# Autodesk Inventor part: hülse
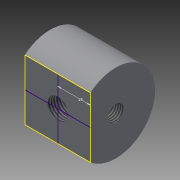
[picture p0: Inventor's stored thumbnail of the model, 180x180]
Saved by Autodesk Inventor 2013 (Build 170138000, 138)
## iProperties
Created: 2012-11
Part Number: hülse
Material: Allgemein
Document SubType Name: Modeling
Designer: macuser
Density: 1 g/cm^3
Author: macuser
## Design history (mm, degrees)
sketch "Skizze1"
  geometry: L1 (0, -42)-(0, 42) reference; L2 (-29.114, 0)-(39.852, 0) reference; L3 (-19.261, 23)-(-19.261, -23); A1 r 30 centre (0, 0) between (-19.261, -23) and (-19.261, 23); 1 further point
  constraints: 2 end point, 2 point on circle, 1 centre point, 1 coincident, 1 perpendicular
  dimensions: "d0" = 60 diameter of A1; "d2" = 46 distance of L3.end L3.start
extrude "Extrusion1" new body sketch "Skizze1" distance "d3" = 50; taper "d4" = 0 deg
sketch "Skizze3"
  geometry: L1 (0, 46)-(0, 0) reference; L2 (0, 0)-(50, 0) reference; L3 (50, 46)-(50, 0) reference; L4 (0, 46)-(50, 46) reference; L5 (0, 23)-(50, 23); L6 (25, 46)-(25, 0)
  constraints: 4 end point, 3 midpoint, 1 perpendicular
  dimensions: "d8" = 25 distance between parallel lines of L3 L6
hole "Bohrung1" diameter "d11" = 16; stored, may be unused: countersink angle "d15" = 90 deg, drill point angle "d17" = 118 deg; dims "d9" = 25, "d10" = 23, "d12" = 100, "d13" = 4, "d14" = 2, "d16" = 8
sketch "Skizze4"
  geometry: C1 r 6 at (0, 0); A1 r 30 centre (0, 0) between (23, -19.261) and (-23, -19.261) reference
  constraints: 1 centre point, 1 coincident
  dimensions: "d38" = 12 diameter of C1
extrude "Extrusion3" cut sketch "Skizze4" distance "d39" = 16; taper "d40" = 0 deg
feature "Gewinde1" dims "d41" = 10, "d42" = 0
sketch "Skizze5"
  geometry: C1 r 6 at (0, 0); A1 r 30 centre (0, 0) between (23, -19.261) and (-23, -19.261) reference
  constraints: 1 centre point, 1 coincident
  dimensions: "d43" = 12 diameter of C1
extrude "Extrusion4" cut sketch "Skizze5" distance "d44" = 16; taper "d45" = 0 deg
feature "Gewinde2" dims "d46" = 10, "d47" = 0
feature "Gewinde3" dims "d48" = 10, "d49" = 0
node "Volumenkörper1"
